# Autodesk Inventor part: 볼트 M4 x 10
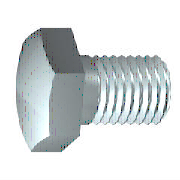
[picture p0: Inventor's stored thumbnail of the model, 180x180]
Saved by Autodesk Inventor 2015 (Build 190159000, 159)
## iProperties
Created: 2012-02
Part Number: 볼트 M4 x 10
Material: 스테인리스강
Description: 6각 머리 나사
Document SubType Name: Modeling
Standard: ISO 4017
Designer: mduedu
Standard Revision: Third edition 1999-08-15
Standards Organization: ISO
Language: ko-KR
Size Designation: M4 x 10
Categories: <MemberInstance><Categories><Category DisplayName="조임쇠" InternalName="e4da775c-781d-43d5-af7c-5136215cf5a6" Mnemonic="FSTN"><Category DisplayName="볼트" InternalN
Density: 8.08 g/cm^3
Appearance: 기본값
IsCustomPart: 0
Author: mduedu
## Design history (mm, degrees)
sketch "스케치1"
  geometry: L1 (0, 3.015)-(0, 2); L2 (2.1, 2)-(10, 2); L3 (10, 2)-(10, 0); L4 (10, 0)-(-0.4, 0); L5 (-2.48, 0)-(12.08, 0) reference; L6 (-0.4, 0)-(-0.4, 3.015); L7 (-0.4, 3.015)-(0, 3.015); L8 (2.1, 2)-(1.67, 2); L9 (1.67, 2)-(0, 2); L10 (0, -0.603)-(0, 3.618) reference
  constraints: 16 end point, 2 collinear, 2 perpendicular, 1 parallel
  dimensions: "d0" = 10 distance between parallel lines of L3 L1 (= NLG); "d1" = 7.9 distance from line of L2.start L3 (= GEL); "d2" = 4 diameter of L2 L4 (= GD); "d9" = 0.4001 distance between parallel lines of L6 L1 (computed from SD); "d10" = 6.03 diameter of L7 L4 (= SD2); "d13" = 0.42952 distance of L2.start L8.end (computed from GAL); "d14" = 4 diameter of L9 L4 (= BDM)
revolve "본체" sketch "스케치1" stored, may be unused: angle "d12" = 90 deg
sketch "스케치2"
  geometry: L1 (0, 4.041)-(3.5, 2.021); L2 (3.5, 2.021)-(3.5, -2.021); L3 (3.5, -2.021)-(0, -4.041); L4 (0, -4.041)-(-3.5, -2.021); L5 (-3.5, -2.021)-(-3.5, 2.021); L6 (-3.5, 2.021)-(0, 4.041); 2 further points
  constraints: 12 end point, 1 coincident, 1 vertical, 11 other
  dimensions: "d11" = 7 distance between parallel lines of L5 L2 (= SW)
extrude "머리" join sketch "스케치2" distance "d3" = 2.4 (= KOH - SD); taper "d4" = 0 deg
sketch "스케치4"
  geometry: L1 (-2.8, 3.5)-(-2.8, 4.041); L2 (-2.8, 4.041)-(-2.487, 4.041); L3 (-2.487, 4.041)-(-2.8, 3.5); L4 (-3.28, 0)-(0.08, 0) reference; L5 (-0.4, 4.041)-(-2.8, 4.041) reference; L6 (-2.8, 2.021)-(-2.8, 4.041) reference
  constraints: 6 end point, 2 collinear, 1 perpendicular, 1 vertical
  dimensions: "d5" = 30 deg angle of L3 L1 (= ANG1); "d19" = 7 diameter of L1.start L4 (= SW0)
revolve "모따기1" sketch "스케치4" stored, may be unused: angle "d21" = 90 deg
workplane "Work Plane1"
body "Solid1"
feature "스레드" dims "d15" = 7.9 (= GEL), "d16" = 0
chamfer "모따기2" distance "d6" = 0.42941 (= -0.5 x SPD + 0.5 x GD); stored, may be unused: second distance "d7" = 0.42952 (computed from GUL), angle "d55" = 45 deg
other parameters: "NLG" = 10 [user parameter; used in 1 equation term], "GD" = 4 (= NND) [user parameter; used in 2 equation terms], "BDM" = 4 (= NND) [user parameter; used in 1 equation term], "KOH" = 2.8 [user parameter; used in 1 equation term], "GEL" = 7.9 [user parameter; used in 2 equation terms], "SW" = 7 [user parameter; used in 2 equation terms], "SW0" = 7 (= SW) [user parameter; used in 1 equation term], "SPD" = 3.14117 (= NND - 1.2269 x PTC) [user parameter; used in 1 equation term], "SD2" = 6.03 [user parameter; used in 2 equation terms], "SD" = 0.4 [user parameter; used in 2 equation terms], "ANG1" = 30 deg [user parameter; used in 1 equation term], "GAL" = 0.42941 (= 0.61345 x PTC) [user parameter; used in 1 equation term], "GUL" = 0.42941 (= 0.61345 x PTC) [user parameter; used in 1 equation term], "d8" = 0, "RR" = 0.2 [user parameter], "d57" = 0, "d58" = 0, "TPU" = 14.28571 (computed from PTC) [user parameter], "GD1" = 3.14117 (= THREADDIA - 1.2269 x PTC) [user parameter], "THREADDIA" = 4 [user parameter; used in 1 equation term], "SDH" = 6.03 (= SD2) [user parameter], "SDHG" = 2.1 [user parameter], "TOA" = 30 deg [user parameter], "PTC" = 0.7 [user parameter; used in 5 equation terms], "NND" = 4 [user parameter; used in 3 equation terms], "E0" = 8.085 [user parameter]
